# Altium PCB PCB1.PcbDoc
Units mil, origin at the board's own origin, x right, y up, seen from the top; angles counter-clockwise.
Board outline 6000 x 4000 mil, 2 copper layers (Top Layer, Bottom Layer); 70 components, 63 nets, 143 pads, 0 vias.
Unrouted connection lines stored in the file: 98.
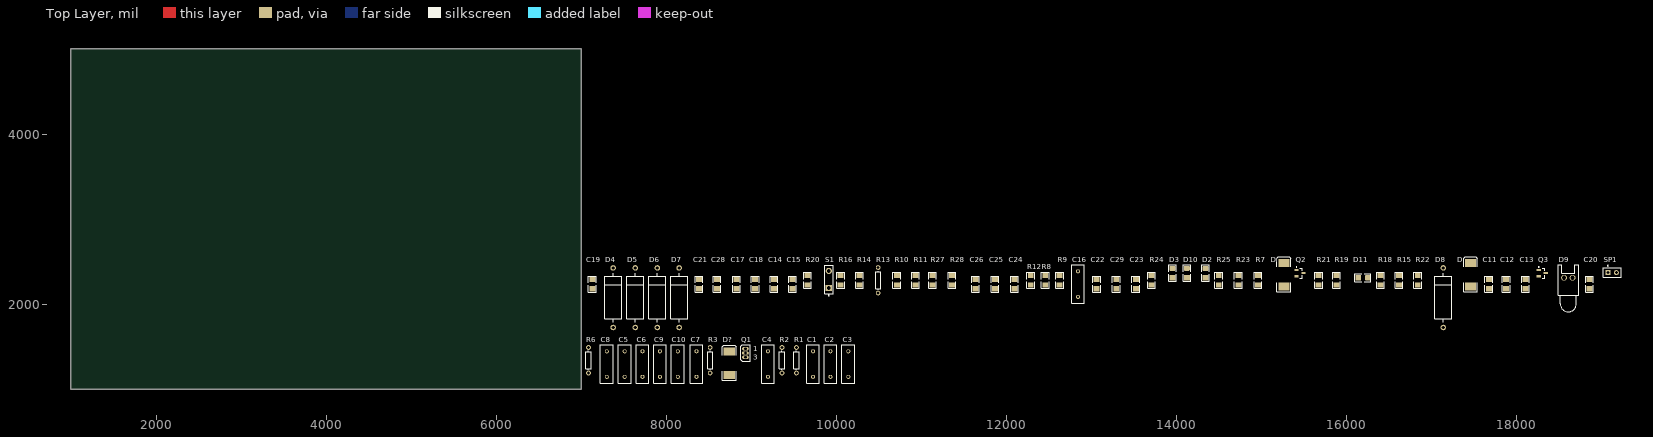
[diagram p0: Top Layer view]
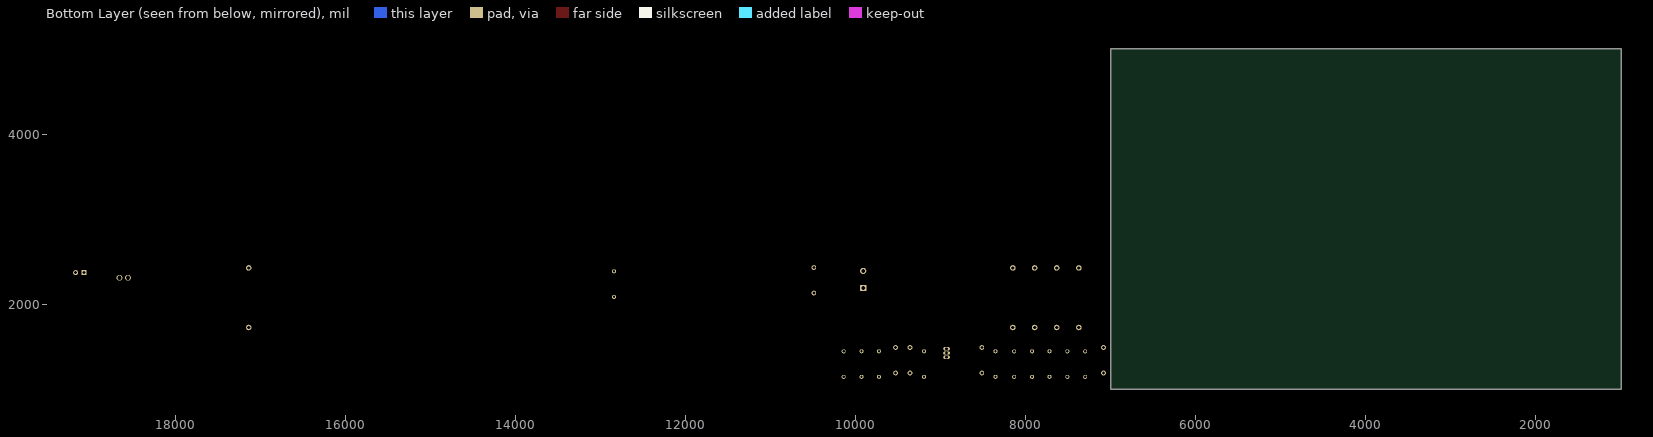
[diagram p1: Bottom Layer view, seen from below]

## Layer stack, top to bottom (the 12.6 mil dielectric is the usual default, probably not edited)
Top Solder: solder mask 0.4, Solder Resist, Dk 3.5
Top Layer: signal copper 1.4
Dielectric 1: dielectric 12.6, FR-4, Dk 4.8
Bottom Layer: signal copper 1.4
Bottom Solder: solder mask 0.4, Solder Resist, Dk 3.5

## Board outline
1000,1000 7000,1000 7000,5000 1000,5000

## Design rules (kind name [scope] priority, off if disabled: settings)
Clearance [All] p1: gap=10 ignorepadtopadclearanceinfootprint=FALSE
DiffPairsRouting [All] p1: maxlimit=10 minlimit=10 mostfreqgap=10 toplayer_minwidth=15 toplayer_maxwidth=15 toplayer_prefwidth=15 bottomlayer_minwidth=15 bottomlayer_maxwidth=15 bottomlayer_prefwidth=15 maxuncoupledlength=500
PolygonConnect [All] p1: connectstyle=Relief reliefconductorwidth=10 reliefentries=4 polygonreliefangle="90 Angle" airgapwidth=10
RoutingVias [All] p1: holewidth=28 width=50 viastyle="Through Hole" minholewidth=28 minwidth=50 maxholewidth=28 maxwidth=50
SolderMaskExpansion [All] p1: expansion=4 istentingtop=FALSE
SupplyNets "Schematic Supply Nets_3" [InNet('3.3V')] p1: voltage=0.000
SupplyNets "Schematic Supply Nets_2" [InNet('5.0V')] p2: voltage=0.000
SupplyNets "Schematic Supply Nets_1" [InNet('GND')] p3: voltage=0.000
SupplyNets "Schematic Supply Nets" [InNet('5V_CAN')] p4: voltage=0.000
Width [All] p1: maxlimit=10 minlimit=10 preferedwidth=10
29 further rules are at their usual default settings.

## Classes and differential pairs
component class Sheet1: C1 C2 C3 C4 C5 C6 C7 C8 C9 C10 D1 D? J1 J2 Q1 R1 R2 R3 R6 TPAD1 U1 U2 U3
differential pair CAN: +CAN_P -CAN_N

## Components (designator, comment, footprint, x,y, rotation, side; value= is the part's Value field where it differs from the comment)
C1 "0.1uF" RAD-0.3 9725,1295 r90 top
C2 "0.1uF" RAD-0.3 9930,1295 r90 top
C3 "2.2uF" RAD-0.3 10140,1295 r90 top
C4 "2.2uF" RAD-0.3 9195,1295 r90 top
C5 "10uF/10V" RAD-0.3 7510,1295 r90 top
C6 "10uF" RAD-0.3 7720,1295 r90 top
C7 "10uF/10V" RAD-0.3 8355,1295 r90 top
C8 "2.2uF" RAD-0.3 7300,1295 r90 top
C9 "10uF" RAD-0.3 7925,1295 r90 top
C10 "10uF" RAD-0.3 8135,1295 r90 top
C11 "10nF" "1206-3D - Cap" 17670,2235 r90 top
C12 "0.1uF" "1206-3D - Cap" 17875,2235 r90 top
C13 "1uF" "1206-3D - Cap" 18100,2235 r90 top
C14 "0.1uF" "1206-3D - Cap" 9265,2235 r90 top
C15 "0.1uF" "1206-3D - Cap" 9485,2235 r90 top
C16 "220mF/3.3V" RAD-0.3 12840,2235 r90 top
C17 "0.1uF" "1206-3D - Cap" 8825,2235 r90 top
C18 "2.2uF" "1206-3D - Cap" 9045,2235 r90 top
C19 "10nF" "1206-3D - Cap" 7130,2235 r90 top
C20 "2.2uF/10V" "1206-3D - Cap" 18855,2235 r90 top
C21 "0.1uF" "1206-3D - Cap" 8385,2235 r90 top
C22 "0.1uF" "1206-3D - Cap" 13060,2235 r90 top
C23 "0.1uF" "1206-3D - Cap" 13520,2235 r90 top
C24 "0.1uF" "1206-3D - Cap" 12095,2235 r90 top
C25 "4.7uF" "1206-3D - Cap" 11865,2235 r90 top
C26 "0.1uF" "1206-3D - Cap" 11635,2235 r90 top
C28 "0.1uF" "1206-3D - Cap" 8595,2235 r90 top
C29 "0.1uF" "1206-3D - Cap" 13290,2235 r90 top
D "Diode" SMC 17455,2345 r90 top
D "Diode" SMC 15260,2345 r90 top
D2 "Red" "1206-3D - LED" 14340,2365 r90 top
D3 "Blue" "1206-3D - LED" 13950,2365 r90 top
D4 "D Zener" DIODE-0.7 7375,2075 r90 top
D5 "D Zener" DIODE-0.7 7635,2075 r90 top
D6 "D Zener" DIODE-0.7 7895,2075 r90 top
D7 "D Zener" DIODE-0.7 8150,2075 r90 top
D8 "BAT54J115" DIODE-0.7 17135,2075 r90 top
D9 "Green" LED-0 18605,2310 r0 top
D10 "Green" "1206-3D - LED" 14120,2365 r90 top
D11 "Red" "1206-3D - LED" 16190,2310 r0 top
D? "Diode" SMC 8740,1305 r90 top
Q1 "MOSFET-N" E3 8930,1425 r0 top
Q2 "2N7002K-7" SOT23_N 15450,2365 r0 top
Q3 "" SOT23_N 18300,2365 r0 top
R1 "120R" AXIAL-0.3 9530,1340 r90 top
R2 "100k" AXIAL-0.3 9360,1340 r90 top
R3 "100k" AXIAL-0.3 8515,1340 r90 top
R6 "5.1k" AXIAL-0.3 7085,1340 r90 top
R7 "330R" 1206-3D-Res 14955,2280 r90 top
R8 "604R" 1206-3D-Res 12455,2280 r90 top
R9 "604R" 1206-3D-Res 12625,2280 r90 top
R10 "5.1K" 1206-3D-Res 10710,2280 r90 top
R11 "5.1K" 1206-3D-Res 10930,2280 r90 top
R12 "604R" 1206-3D-Res 12285,2280 r90 top
R13 "0" AXIAL-0.3 10490,2280 r90 top
R14 "100k" 1206-3D-Res 10270,2280 r90 top
R15 "100K" 1206-3D-Res 16615,2280 r90 top
R16 "100k" 1206-3D-Res 10050,2280 r90 top
R18 "0" 1206-3D-Res 16395,2280 r90 top
R19 "330" 1206-3D-Res 15880,2280 r90 top
R20 "100K" 1206-3D-Res 9660,2280 r90 top
R21 "0" 1206-3D-Res 15670,2280 r90 top
R22 "330" 1206-3D-Res 16835,2280 r90 top
R23 "0" 1206-3D-Res 14725,2280 r90 top
R24 "100K" 1206-3D-Res 13705,2280 r90 top
R25 "100K" 1206-3D-Res 14495,2280 r90 top
R27 "5.1K" 1206-3D-Res 11130,2280 r90 top
R28 "5.1K" 1206-3D-Res 11360,2280 r90 top
S1 "SW-PB" SPST-2 9910,2290 r90 top
SP1 "ST-03CH" PIN2 19070,2370 r0 top

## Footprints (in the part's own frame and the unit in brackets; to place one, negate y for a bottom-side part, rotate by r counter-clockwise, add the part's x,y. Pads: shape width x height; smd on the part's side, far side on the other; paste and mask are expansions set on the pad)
"1206-3D - Cap" [mil]
  rect 60x70 smd: 1(-55,0) 2(55,0)
  silkscreen extent -95,-45 95,45, body extent -63,-30 63,33, height 39
"1206-3D - LED" [mil]
  rect 60x70 smd: 1(-55,0)
  rrect50% 60x70 smd: 2(55,0)
  silkscreen extent -95,-45 95,45, body extent -62,-31 64,32, height 43
1206-3D-Res [mil]
  rect 60x70 smd: 1(-55,0) 2(55,0)
  silkscreen extent -95,-45 95,45, body extent -63,-31 63,31, height 39
AXIAL-0.3 [mm] "Axial Device, Thru-Hole; 2 Leads; 0.3 in Pin Spacing"
  round 1.4 hole 0.85: 1(-3.81,0) 2(3.81,0)
  silkscreen extent -2.77,-0.76 2.77,0.76
DIODE-0.7 [mm] "Diode, Thru-Hole; 2 Leads; 0.7 in Pin Spacing"
  round 1.65 hole 1: 1(-8.89,0) 2(8.89,0)
  silkscreen extent -7.37,-2.54 7.37,2.54
E3 [mm] "TO, Flat Index; 3 In-Line, Axial Leads; Body Dia. 4.6mm; Lead Dia. 0.5 mm (max)"
  oval 2x1 hole 0.8: 1(0,1.27) 2(0,0) 3(0,-1.27)
  silkscreen extent -1.41,-2.41 1.41,2.41
LED-0 [mil] "LED; 2 Leads"
  round 70 hole 50: 1(50,0) 2(-50,0)
  silkscreen extent -120,-400 120,150
PIN2 [mm] "Photosensitive Diode; 2 Leads"
  rect 1.5x1.5 hole 0.9: 1(0,0)
  round 1.5 hole 0.9: 2(2.54,0)
  silkscreen extent -1.4,-1.4 3.94,2.17
RAD-0.3 [mm] "Radial Cap, Thru-Hole; 2 Leads; 0.3 in Pin Spacing"
  round 1.2 hole 0.7: 1(-3.81,0) 2(3.81,0)
  silkscreen extent -5.71,-1.91 5.71,1.91
SMC [mm] "DO-214-AB/SMC; 2 C-Bend Leads; Body 7.9 x 5.9 mm, inc. leads (LxW)"
  rect 2.4x3.3 smd: 1(-3.475,0) 2(3.475,0)
  silkscreen extent -5.07,-2.05 5.43,2.05
SOT23_N [mm] "SOT23, 3-Leads, Body 2.9x1.3mm, Pitch 0.95mm, Lead Span 2.3mm, IPC Medium Density"
  rect 1.3x0.6 smd: 1(-1.05,0.95) 2(-1.05,-0.95) 3(1.05,0)
  silkscreen extent -1.17,-1.5 0.7,1.92, body extent -0.7,-1.5 0.7,1.5, height 1.1
SPST-2 [mm] "Switch; 2 Leads"
  rect 1.85x1.85 hole 1.1: 1(-2.54,0)
  round 1.85 hole 1.1: 2(2.54,0)
  silkscreen extent -4.89,-1.27 4.28,1.27

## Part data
C1 C2 C3 C4 C5 C6 C7 C8 C9 C10 C11 C12 C13 C14 C15 C16 C17 C18 C19 C20 C21 C22 C23 C24 C25 C26 C28 C29: library part Cap, "Capacitor"
D D D?: "Default Diode"
D2 D3 D9 D10 D11: library part LED0, "Typical INFRARED GaAs LED"
D4 D5 D6 D7: "Zener Diode"
D8: library part "D Zener", "Zener Diode"
Q1: "N-Channel MOSFET"
Q2 Q3: library part MOSFET-N, "N-Channel MOSFET"
R1 R2 R3 R6 R7 R8 R9 R10 R11 R12 R13 R14 R15 R16 R18 R19 R20 R21 R22 R23 R24 R25 R27 R28: library part Res1, "Resistor"
S1: "Switch"
SP1: library part Speaker, "Loudspeaker"

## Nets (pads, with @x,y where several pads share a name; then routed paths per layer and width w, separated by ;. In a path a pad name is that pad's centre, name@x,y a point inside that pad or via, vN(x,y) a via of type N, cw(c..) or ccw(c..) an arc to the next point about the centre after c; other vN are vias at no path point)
3.3V: C1.2 C6.2 C9.2 C10.2 C14.2 C15.2 C17.2 C18.2 C19.2 C21.2 C22.2 C23.2 C24.2 C26.2 C28.2 C29.2 R2.2 R10.1 R11.1 R16.1 R24.2 R27.1 R28.1 S1.1
5.0V: C2.2 C5.2 C7.2 C20.2 D2.1 D3.1 D9.1 D10.1 D11.1 SP1.2
5V_CAN: C3.2 C4.2 C8.2
BOOT0: R14.1
BTN_SAFETY: R20.1 S1.2
BUZZER_TIM2_CH1: Q3.2 R15.1
CAN1_RX: 
CAN1_TX: 
CAN_N: D?.1 Q1.3
CAN_P: R1.2
CAN_SILENT: 
CAN_TERM: Q1.2 R3.2
GND: C1.1 C2.1 C3.1 C4.1 C5.1 C6.1 C7.1 C8.1 C9.1 C10.1 C11.1 C12.1 C13.1 C14.1 C15.1 C16.1 C17.1 C18.1 C19.1 C20.1 C21.1 C22.1 C23.1 C24.1 C25.1 C26.1 C28.1 C29.1 D4.1 D5.1 D6.1 D7.1 D.1 Q2.3 Q3.3 R3.1 R6.1 R14.2 R15.2 R18.2 R20.2 R25.1
I2C1_SCL_MAG: 
I2C1_SDA_MAG: R10.2 R11.2
I2C2_SCL_BARO: R28.2
I2C2_SDA_BARO: R27.2
LED_SAFETY: R7.2
LED_TIM1_CH1_RED: R9.2
LED_TIM1_CH2_GREEN: R8.2
LED_TIM1_CH3_BLUE: R12.2
NetC11_2: C11.2 C12.2 C13.2 D8.1
NetC16_2: C16.2 R23.1
NetD2_2: D2.2 R9.1
NetD3_2: D3.2 R12.1
NetD8_2: D8.2 R19.2
NetD9_2: D9.2 R22.2
NetD10_2: D10.2 R8.1
NetD11_2: D11.2 R7.1
NetD?_2: D?.2 Q1.1 R1.1
NetD_2: D.2@17455,2481.81 Q3.1 SP1.1
NetQ2_2: Q2.2 R25.2
NetR2_1: R2.1
NetR6_2: R6.2
NetR13_1: R13.1
NetR13_2: R13.2
NetR18_1: R18.1
NetR19_1: R19.1 R21.2 R23.2
NetR21_1: R21.1
NetR24_1: R24.1
NetTP1_1: 
NetTP2_1: 
NetTP3_1: 
NetTP4_1: 
NetTP5_1: 
NetTPAD1_1: 
NetTPAD6_1: 
NetTPAD7_1: 
NRST: R16.2
SP11_CS_ICM42688P: 
SP11_DRDY_ICM42688P: 
SP11_FSYNC_ICM42688P_TIM10_CH1: 
SP11_MIS0: 
SP11_MISO: 
SP11_MOSI: 
SP11_SCK: 
SYS_SWCLK: D4.2
SYS_SWDIO: D5.2
USART1_GPS_RX: 
USART1_GPS_TX: 
USART2-RX: D6.2
USART2-TX: D7.2
VCAP: C25.2
pads on no net: D.2@15260,2481.81 Q2.1 R22.1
